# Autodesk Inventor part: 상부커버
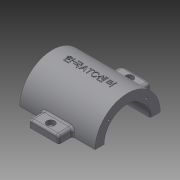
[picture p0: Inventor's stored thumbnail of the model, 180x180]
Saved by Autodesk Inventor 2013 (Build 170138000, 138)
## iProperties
Created: 2015-12
Part Number: 상부커버
Material: 일반
Document SubType Name: Modeling
Designer: mduedu
Density: 2.71 g/cm^3
Mass: 190.123 g
Surface Area: 187.8 cm^2
Volume: 70.1561 cm^3
Author: mduedu
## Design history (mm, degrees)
sketch "스케치1"
  geometry: L1 (45, 40)-(-45, 40); L2 (-45, 40)-(-45, -40); L3 (-45, -40)-(45, -40); L4 (45, -40)-(45, 40); L5 (45, 40)-(-45, -40); L6 (-45, 40)-(45, -40); 2 further points
  constraints: 12 end point, 2 midpoint, 2 parallel, 1 coincident, 1 horizontal, 1 perpendicular, 3 other
  dimensions: "d0" = 90 distance of L2.end L3.end; "d2" = 80 distance of L1.end L2.end
extrude "돌출1" new body sketch "스케치1" distance "d3" = 10; taper "d4" = 0 deg
sketch "스케치2"
  geometry: C1 r 32.5 at (80, 0); 1 further point
  constraints: 1 centre point
  dimensions: "d5" = 65 diameter of C1; "d116" = 80 distance of point (0, 0) C1.centre
extrude "돌출2" join sketch "스케치2" stored distance "d7" = 75; taper "d8" = 0 deg
sketch "스케치3"
  geometry: L1 (-27.5, -20)-(27.5, -20); L2 (27.5, -20)-(27.5, 20); L3 (27.5, 20)-(-27.5, 20); L4 (-27.5, 20)-(-27.5, -20); L5 (-27.5, -20)-(27.5, 20); L6 (27.5, -20)-(-27.5, 20); 1 further point
  constraints: 12 end point, 2 midpoint, 2 parallel, 1 horizontal, 1 perpendicular
  dimensions: "d9" = 55 distance of L2.end L3.end; "d11" = 40 distance of L1.end L2.end
extrude "돌출3" new body sketch "스케치3" stored distance "d12" = 75; taper "d13" = 0 deg
fillet "모깎기1"
fillet "모깎기2"
feature "결합1"
  node "솔리드2"
sketch "스케치4"
  geometry: L1 (-37.5, 47.5)-(37.5, 47.5) reference; L2 (32.5, 47.5)-(40.208, 10); L3 (37.5, 47.5)-(37.5, 112.5) reference; L4 (60.208, 0)-(60.208, 10) reference; L5 (60.208, 10)-(-60.208, 10) reference; 1 further point
  constraints: 2 end point, 2 point on line
  dimensions: "d15" = 5 distance from line of L2.start L3; "d117" = 20 distance from line of L2.end L4
sketch "스케치5"
  geometry: L1 (10, 35.208)-(56.729, 22.687); L2 (0, 60.208)-(10, 60.208) reference; L3 (10, -60.208)-(10, 60.208) reference; 2 further points
  constraints: 2 end point, 1 point on line, 2 other
  dimensions: "d118" = 25 distance from line of L1.start L2; "d119" = 75 deg angle of L1 L3
feature "리브1" dims "d19" = 1, "d20" = 6, "d21" = 0, "d22" = 0, "d23" = 1, "d24" = 1
feature "리브2" dims "d25" = 1, "d26" = 6, "d27" = 0, "d28" = 0, "d29" = 1, "d30" = 1
fillet "모깎기4" dims "d31" = 2
fillet "모깎기5" dims "d32" = 2
fillet "모깎기6" dims "d33" = 2
sketch "스케치6"
  geometry: L1 (0, 0)-(-32.88, 32.88); L2 (0, 0)-(-46.5, 0); A1 r 46.5 centre (0, 0) between (-32.88, 32.88) and (-46.5, 0); 5 further points
  constraints: 4 end point, 2 coincident, 2 point on circle, 1 centre point, 1 horizontal, 5 other
  dimensions: "d120" = 93 diameter of A1; "d122" = 45 deg angle of L1 L2; "d126" = 360 deg dimension on point (0, 0) point (-32.88, 32.88) (derived)
hole "구멍1" sketch "스케치6" at (-32.88, 32.88), (-32.88, -32.88), (32.88, -32.88), (32.88, 32.88) diameter "d34" = 7; stored, may be unused: countersink angle "d38" = 90 deg, drill point angle "d40" = 118 deg; dims "d35" = 6, "d36" = 12, "d37" = 3, "d39" = 8
fillet "모깎기13" dims "d131" = 3
hole "구멍2" diameter "d44" = 45; stored, may be unused: countersink angle "d48" = 90 deg, drill point angle "d50" = 118 deg; dims "d42" = 10, "d43" = 10, "d45" = 6, "d46" = 4, "d47" = 2, "d49" = 8
sketch "스케치7" dims "d52" = 26.5
  geometry: L1 (0, 0)-(32.5, 0); L2 (0, 0)-(22.981, 22.981); A1 r 32.5 centre (0, 0) between (32.5, 0) and (22.981, 22.981) reference; 3 further points
  constraints: 4 end point, 2 point on circle, 1 coincident, 1 horizontal, 1 point on line, 3 other
  dimensions: "d51" = 45 deg angle of L2 L1
hole "구멍3" sketch "스케치7" at (18.738, 18.738) diameter "d54" = 2.459; stored, may be unused: countersink angle "d58" = 90 deg, drill point angle "d60" = 118 deg; dims "d55" = 8, "d56" = 4, "d57" = 2, "d59" = 10
sketch "스케치8"
  geometry: L1 (72.5, 31.623)-(72.5, 46); L2 (72.5, 46)-(87.5, 46); L3 (87.5, 46)-(87.5, 31.623); A1 r 32.5 centre (80, 0) between (87.5, 31.623) and (72.5, 31.623) reference; 2 further points
  constraints: 6 end point, 2 point on circle, 1 horizontal, 1 midpoint, 1 parallel, 1 vertical, 1 vertical alignment
  dimensions: "d64" = 15 distance of L1.end L2.end; "d66" = 46 distance from line of L2 A1.centre
extrude "돌출4" join sketch "스케치8" stored distance "d67" = 30; taper "d68" = 0 deg
fillet "모깎기8" dims "d69" = 3
fillet "모깎기9" dims "d70" = 2
node "작업 평면2"
sketch "스케치16"
  geometry: L1 (33.166, 72.5)-(44, 72.5) reference; L2 (42.5, 72.5)-(28.53, 64.434); L3 (46, 75.5)-(46, 84.5) reference; 2 further points
  constraints: 2 end point, 1 point on line, 2 other
  dimensions: "d138" = 30 deg angle of L2 L1; "d139" = 3.5 distance from line of L2.start L3
feature "리브3" sketch "스케치16" dims "d140" = 1, "d141" = 3, "d142" = 0, "d143" = 0, "d144" = 1, "d145" = 1
fillet "모깎기14" dims "d146" = 1
fillet "모깎기15" dims "d147" = 1
sketch "스케치9"
  geometry: L1 (-76, -110)-(76, -110); L2 (76, -110)-(76, 0); L3 (76, 0)-(-76, 0); L4 (-76, 0)-(-76, -110); L5 (-46, 4.5)-(-46, -4.5) reference; L6 (-60.208, -80)-(60.208, -80) reference; C1 r 32.5 at (0, 0) reference; 2 further points
  constraints: 8 end point, 2 parallel, 1 coincident, 1 horizontal, 1 midpoint, 1 perpendicular
  dimensions: "d72" = 30 distance between parallel lines of L4 L5; "d148" = 30 distance between parallel lines of L6 L1
extrude "돌출5" cut sketch "스케치9" stored distance "d73" = 0; taper "d74" = 0 deg
node "작업 평면3"
sketch "스케치17"
  geometry: 2 further points
  constraints: 1 coincident, 1 other
feature "엠보싱1" sketch "스케치17" dims "d150" = 0.5, "d151" = 0
sketch "스케치18"
  geometry: L1 (-3, -1.039)-(-3, -10.834) reference; L2 (27, -10.834)-(27, -1.039) reference; L3 (0, -12.834)-(24, -12.834) reference; L4 (-3, -5.936)-(27, -5.936); L5 (12, -12.834)-(12, 33.166); 1 further point
  constraints: 4 end point, 4 midpoint, 1 perpendicular, 1 point on line
hole "구멍8" sketch "스케치18" at (12, -5.936) diameter "d152" = 4.5; stored, may be unused: countersink angle "d156" = 90 deg, drill point angle "d158" = 118 deg; dims "d153" = 6, "d154" = 8, "d155" = 4.6, "d157" = 8
chamfer "모따기2" distance "d159" = 1; stored, may be unused: second distance "d160" = 2, angle "d161" = 45 deg
node "솔리드1"
mirror "대칭1"
mirror "대칭2"
pattern_circular "원형 패턴1" dims angle "d62" = 360 deg
mirror "대칭3"
mirror "대칭7"
mirror "대칭4"
mirror "대칭8"
other parameters: "d137" = -5
